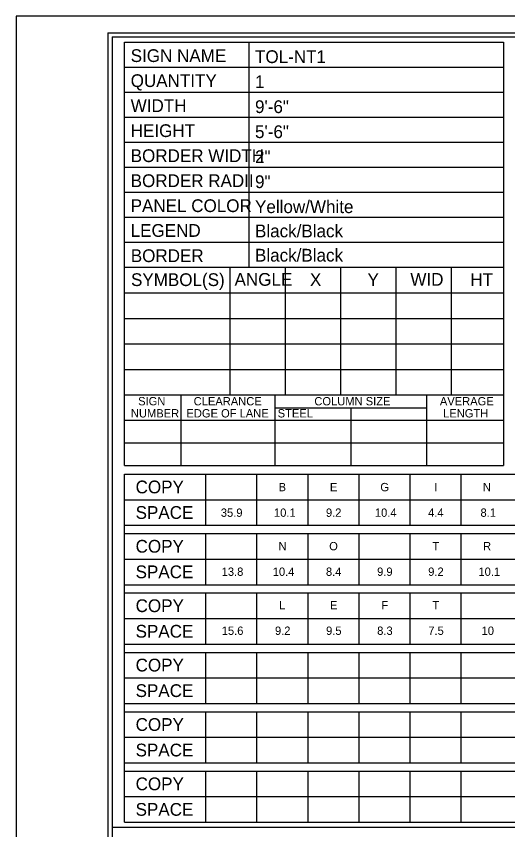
# Model space of a CAD drawing. Extents: x 17890628 to 17890844, y 17897508 to 17897992.
# Drawn here: x 17890700.47 to 17890726.2, y 17897557.55 to 17897600.12 of the extents above; entities that cross this region are included whole.
import ezdxf

# ---------------------------------------------------------------- set-up
doc = ezdxf.new("R2010")
doc.units = 0
for name, color, linetype in [('GSSign', 7, 'Continuous'), ('PlotBorder_dp', 7, 'Continuous'), ('SheetBorder_dp', 7, 'Continuous'), ('SheetLinesMisc2_dp', 7, 'Continuous'), ('TextMinor', 7, 'Continuous')]:
    doc.layers.add(name, color=color, linetype=linetype)

msp = doc.modelspace()

# ---------------------------------------------------------------- linework, layer by layer
at = {"layer": 'PlotBorder_dp'}
msp.add_lwpolyline([(17890700.471, 17897507.741), (17890844.259, 17897507.741), (17890844.259, 17897600.116), (17890700.471, 17897600.116)], close=True, dxfattribs=at)
at = {"layer": 'SheetBorder_dp'}
for q in [(17890705.263, 17897508.613), (17890839.466, 17897599.245)]:
    msp.add_line((17890705.263, 17897599.245), q, dxfattribs=at)
at = {"layer": 'SheetLinesMisc2_dp'}
for p, q in [((17890705.5, 17897599.039), (17890839.233, 17897599.039)), ((17890705.5, 17897599.039), (17890705.5, 17897515.791)), ((17890706.142, 17897576.606), (17890706.142, 17897598.762)), ((17890706.142, 17897598.762), (17890725.973, 17897598.762)), ((17890712.643, 17897598.762), (17890712.643, 17897586.981)), ((17890725.973, 17897598.762), (17890725.973, 17897576.606)), ((17890706.142, 17897597.453), (17890725.973, 17897597.453)), ((17890706.142, 17897596.144), (17890725.973, 17897596.144)), ((17890706.142, 17897594.836), (17890725.973, 17897594.836)), ((17890706.142, 17897593.527), (17890725.973, 17897593.527)), ((17890706.142, 17897592.218), (17890725.973, 17897592.218)), ((17890706.142, 17897590.91), (17890725.973, 17897590.91)), ((17890706.142, 17897589.601), (17890716.057, 17897589.601)), ((17890716.057, 17897589.601), (17890725.973, 17897589.601)), ((17890706.142, 17897588.293), (17890716.057, 17897588.293)), ((17890716.057, 17897588.293), (17890725.973, 17897588.293)), ((17890706.141, 17897586.981), (17890725.973, 17897586.981)), ((17890711.644, 17897586.981), (17890711.644, 17897580.3)), ((17890714.542, 17897586.981), (17890714.542, 17897580.3)), ((17890717.44, 17897586.981), (17890717.44, 17897580.3)), ((17890720.337, 17897586.981), (17890720.337, 17897580.3)), ((17890723.235, 17897586.981), (17890723.235, 17897580.3)), ((17890706.141, 17897585.645), (17890725.973, 17897585.645)), ((17890706.141, 17897584.308), (17890725.973, 17897584.308)), ((17890706.141, 17897582.972), (17890725.973, 17897582.972)), ((17890706.141, 17897581.636), (17890725.973, 17897581.636)), ((17890706.141, 17897580.3), (17890725.973, 17897580.3)), ((17890709.08, 17897580.3), (17890709.08, 17897576.607)), ((17890714.015, 17897580.3), (17890714.015, 17897576.607)), ((17890721.947, 17897580.3), (17890721.947, 17897576.607)), ((17890714.015, 17897579.619), (17890721.947, 17897579.619)), ((17890717.981, 17897579.619), (17890717.981, 17897576.607)), ((17890706.141, 17897578.98), (17890725.973, 17897578.98)), ((17890706.141, 17897577.793), (17890725.973, 17897577.793)), ((17890706.142, 17897576.606), (17890725.973, 17897576.606)), ((17890706.142, 17897576.15), (17890771.912, 17897576.15)), ((17890706.142, 17897557.939), (17890706.142, 17897576.15)), ((17890710.375, 17897576.15), (17890710.375, 17897573.478)), ((17890713.051, 17897576.15), (17890713.051, 17897573.478)), ((17890715.727, 17897576.15), (17890715.727, 17897573.478)), ((17890718.402, 17897576.15), (17890718.402, 17897573.478)), ((17890721.077, 17897576.15), (17890721.077, 17897573.478)), ((17890723.753, 17897576.15), (17890723.753, 17897573.478)), ((17890706.142, 17897574.814), (17890771.912, 17897574.814)), ((17890706.142, 17897573.478), (17890771.912, 17897573.478)), ((17890706.142, 17897573.042), (17890771.912, 17897573.042)), ((17890710.375, 17897573.042), (17890710.375, 17897570.37)), ((17890713.051, 17897573.042), (17890713.051, 17897570.37)), ((17890715.727, 17897573.042), (17890715.727, 17897570.37)), ((17890718.402, 17897573.042), (17890718.402, 17897570.37)), ((17890721.077, 17897573.042), (17890721.077, 17897570.37)), ((17890723.753, 17897573.042), (17890723.753, 17897570.37)), ((17890706.142, 17897571.706), (17890771.912, 17897571.706)), ((17890706.142, 17897570.37), (17890771.912, 17897570.37)), ((17890706.142, 17897569.935), (17890771.912, 17897569.935)), ((17890710.375, 17897569.935), (17890710.375, 17897567.263)), ((17890713.051, 17897569.935), (17890713.051, 17897567.263)), ((17890715.727, 17897569.935), (17890715.727, 17897567.263)), ((17890718.402, 17897569.935), (17890718.402, 17897567.263)), ((17890721.077, 17897569.935), (17890721.077, 17897567.263)), ((17890723.753, 17897569.935), (17890723.753, 17897567.263)), ((17890706.142, 17897568.598), (17890771.912, 17897568.598)), ((17890706.142, 17897567.263), (17890771.912, 17897567.263)), ((17890706.142, 17897566.827), (17890771.912, 17897566.827)), ((17890710.375, 17897566.827), (17890710.375, 17897564.154)), ((17890713.051, 17897566.827), (17890713.051, 17897564.154)), ((17890715.727, 17897566.827), (17890715.727, 17897564.154)), ((17890718.402, 17897566.827), (17890718.402, 17897564.154)), ((17890721.077, 17897566.827), (17890721.077, 17897564.154)), ((17890723.753, 17897566.827), (17890723.753, 17897564.154)), ((17890706.142, 17897565.49), (17890771.912, 17897565.49)), ((17890706.142, 17897564.154), (17890771.912, 17897564.154)), ((17890706.142, 17897563.719), (17890771.912, 17897563.719)), ((17890710.375, 17897563.719), (17890710.375, 17897561.047)), ((17890713.051, 17897563.719), (17890713.051, 17897561.047)), ((17890715.727, 17897563.719), (17890715.727, 17897561.047)), ((17890718.402, 17897563.719), (17890718.402, 17897561.047)), ((17890721.077, 17897563.719), (17890721.077, 17897561.047)), ((17890723.753, 17897563.719), (17890723.753, 17897561.047)), ((17890706.142, 17897562.383), (17890771.912, 17897562.383)), ((17890706.142, 17897561.047), (17890771.912, 17897561.047)), ((17890706.142, 17897560.611), (17890771.912, 17897560.611)), ((17890710.375, 17897560.611), (17890710.375, 17897557.939)), ((17890713.051, 17897560.611), (17890713.051, 17897557.939)), ((17890715.727, 17897560.611), (17890715.727, 17897557.939)), ((17890718.402, 17897560.611), (17890718.402, 17897557.939)), ((17890721.077, 17897560.611), (17890721.077, 17897557.939)), ((17890723.753, 17897560.611), (17890723.753, 17897557.939)), ((17890706.142, 17897559.276), (17890771.912, 17897559.276)), ((17890705.5, 17897557.675), (17890839.233, 17897557.675)), ((17890706.142, 17897557.939), (17890771.912, 17897557.939))]:
    msp.add_line(p, q, dxfattribs=at)

# ---------------------------------------------------------------- texts
at = {"layer": 'GSSign'}
for s, height, p in [('TOL-NT1', 0.6667, (17890712.971, 17897597.668)), ('1', 0.667, (17890712.971, 17897596.36)), ('9\'-6"', 0.6667, (17890712.971, 17897595.051)), ('5\'-6"', 0.6667, (17890712.971, 17897593.742)), ('2"', 0.6667, (17890712.971, 17897592.434)), ('9"', 0.6667, (17890712.971, 17897591.125)), ('Yellow/White', 0.66667, (17890712.971, 17897589.816)), ('Black/Black', 0.66667, (17890712.971, 17897588.548)), ('Black/Black', 0.66667, (17890712.971, 17897587.279)), ('B', 0.436, (17890714.205, 17897575.258)), ('E', 0.436, (17890716.89, 17897575.258)), ('G', 0.436, (17890719.531, 17897575.258)), ('I', 0.436, (17890722.358, 17897575.258)), ('N', 0.436, (17890724.899, 17897575.258)), ('35.9', 0.4357, (17890711.18, 17897573.922)), ('10.1', 0.4357, (17890713.963, 17897573.922)), ('9.2', 0.4357, (17890716.683, 17897573.922)), ('10.4', 0.4357, (17890719.246, 17897573.922)), ('4.4', 0.4357, (17890722.031, 17897573.922)), ('8.1', 0.4357, (17890724.774, 17897573.922)), ('N', 0.436, (17890714.201, 17897572.169)), ('O', 0.436, (17890716.853, 17897572.169)), ('T', 0.436, (17890722.256, 17897572.169)), ('R', 0.436, (17890724.909, 17897572.169)), ('13.8', 0.4357, (17890711.225, 17897570.832)), ('10.4', 0.4357, (17890713.899, 17897570.832)), ('8.4', 0.4357, (17890716.684, 17897570.832)), ('9.9', 0.4357, (17890719.362, 17897570.832)), ('9.2', 0.4357, (17890722.037, 17897570.832)), ('10.1', 0.4357, (17890724.668, 17897570.832)), ('L', 0.436, (17890714.236, 17897569.079)), ('E', 0.436, (17890716.898, 17897569.079)), ('F', 0.436, (17890719.581, 17897569.079)), ('T', 0.436, (17890722.26, 17897569.079)), ('15.6', 0.4357, (17890711.228, 17897567.743)), ('9.2', 0.4357, (17890714.015, 17897567.743)), ('9.5', 0.4357, (17890716.69, 17897567.743)), ('8.3', 0.4357, (17890719.366, 17897567.743)), ('7.5', 0.4357, (17890722.041, 17897567.743)), ('10', 0.4357, (17890724.832, 17897567.743))]:
    msp.add_text(s, height=height, dxfattribs=at).set_placement(p)
at = {"layer": 'TextMinor'}
for s, height, p in [('SIGN NAME', 0.6667, (17890706.461, 17897597.722)), ('QUANTITY', 0.6667, (17890706.461, 17897596.413)), ('WIDTH', 0.6667, (17890706.461, 17897595.104)), ('HEIGHT', 0.6667, (17890706.461, 17897593.796)), ('BORDER WIDTH', 0.66667, (17890706.461, 17897592.487)), ('BORDER RADII', 0.66667, (17890706.461, 17897591.178)), ('PANEL COLOR', 0.66667, (17890706.461, 17897589.87)), ('LEGEND', 0.6667, (17890706.461, 17897588.573)), ('BORDER', 0.6667, (17890706.467, 17897587.253)), ('SYMBOL(S)', 0.6667, (17890706.478, 17897585.998)), ('ANGLE', 0.6667, (17890711.899, 17897586.012)), ('X', 0.667, (17890715.846, 17897585.998)), ('Y', 0.667, (17890718.859, 17897585.998)), ('WID', 0.6667, (17890721.103, 17897586.012)), ('HT', 0.6667, (17890724.244, 17897586)), ('SIGN', 0.4357, (17890706.852, 17897579.755)), ('CLEARANCE', 0.4357, (17890709.759, 17897579.753)), ('COLUMN SIZE', 0.43573, (17890716.077, 17897579.753)), ('AVERAGE', 0.4357, (17890722.648, 17897579.753)), ('NUMBER', 0.4357, (17890706.473, 17897579.121)), ('EDGE OF LANE', 0.43573, (17890709.38, 17897579.121)), ('STEEL    ', 0.4357, (17890714.156, 17897579.121)), ('LENGTH', 0.4357, (17890722.817, 17897579.121)), ('COPY', 0.6667, (17890706.719, 17897575.15)), ('SPACE', 0.6667, (17890706.719, 17897573.814)), ('COPY', 0.6667, (17890706.719, 17897572.046)), ('SPACE', 0.6667, (17890706.719, 17897570.709)), ('COPY', 0.6667, (17890706.719, 17897568.935)), ('SPACE', 0.6667, (17890706.719, 17897567.599)), ('COPY', 0.6667, (17890706.719, 17897565.828)), ('SPACE', 0.6667, (17890706.719, 17897564.491)), ('COPY', 0.6667, (17890706.719, 17897562.719)), ('SPACE', 0.6667, (17890706.719, 17897561.383)), ('COPY', 0.6667, (17890706.719, 17897559.613)), ('SPACE', 0.6667, (17890706.719, 17897558.276))]:
    msp.add_text(s, height=height, dxfattribs=at).set_placement(p)

doc.saveas('drawing.dxf')
